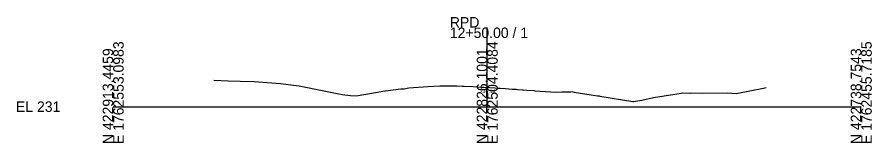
# Model space of a CAD drawing. Extents: x -26 to 203, y -10 to 3024.
# Drawn here: x -25.7 to 202.8, y 2990.3 to 3024 of the extents above; entities that cross this region are included whole.
import ezdxf

# ---------------------------------------------------------------- set-up
doc = ezdxf.new("R2010")
doc.units = 0
for name, color, linetype in [('Default', 7, 'Continuous'), ('Exist Cross Section Cell', 7, 'Continuous'), ('Exist XS Center Line Elevation Label', 7, 'Continuous'), ('Exist XS Ground Line', 7, 'Continuous')]:
    doc.layers.add(name, color=color, linetype=linetype)

msp = doc.modelspace()

# ---------------------------------------------------------------- linework, layer by layer
at = {"layer": 'Exist Cross Section Cell'}
for p, q in [((100, 3000), (100, 3021.18)), ((0, 3000), (100, 3000)), ((100, 3000), (200, 3000))]:
    msp.add_line(p, q, dxfattribs=at)
at = {"layer": 'Exist XS Ground Line'}
msp.add_lwpolyline([(26.9, 3007.06), (30.7, 3006.92), (33.97, 3006.82), (37.7, 3006.74), (44.76, 3006.21), (48.92, 3005.68), (49.74, 3005.54), (56.27, 3004.22), (61.19, 3003.3), (63.44, 3002.98), (64.97, 3002.87), (70.11, 3003.81), (72.64, 3004.25), (72.79, 3004.21), (76.9, 3004.78), (77.8, 3004.8), (79.03, 3005.08), (84.09, 3005.39), (87.33, 3005.54), (88.23, 3005.59), (88.43, 3005.59), (89.69, 3005.6), (90.59, 3005.6), (91.26, 3005.6), (91.31, 3005.6), (91.32, 3005.6), (91.84, 3005.58), (93.31, 3005.51), (93.46, 3005.5), (93.79, 3005.48), (96.28, 3005.36), (98.29, 3005.25), (98.82, 3005.22), (99.12, 3005.2), (100.67, 3005.1), (102.01, 3005.02), (102.53, 3004.99), (103.46, 3004.93), (104.89, 3004.83), (106.68, 3004.72), (107.72, 3004.65), (108.13, 3004.62), (109.39, 3004.54), (109.63, 3004.52), (110.59, 3004.44), (112.46, 3004.29), (112.53, 3004.29), (112.54, 3004.29), (112.69, 3004.28), (118.43, 3003.85), (119.95, 3004.02), (122.31, 3004.02), (122.62, 3004.06), (123.24, 3003.91), (129.52, 3002.93), (129.88, 3002.88), (130.13, 3002.84), (138.9, 3001.42), (139.19, 3001.38), (139.67, 3001.49), (141.29, 3001.76), (144.48, 3002.42), (150.13, 3003.33), (151.83, 3003.6), (152.2, 3003.68), (154.16, 3003.63), (154.25, 3003.62), (154.58, 3003.74), (157.57, 3003.58), (164.23, 3003.67), (166.53, 3003.55), (170.67, 3004.37), (173.88, 3004.96), (174.58, 3005.1)], dxfattribs=at)
msp.add_lwpolyline([(26.9, 3007.06), (30.7, 3006.92), (33.97, 3006.82), (37.7, 3006.74), (44.76, 3006.21), (48.92, 3005.68), (49.74, 3005.54), (56.27, 3004.22), (61.19, 3003.3), (63.44, 3002.98), (64.97, 3002.87), (70.11, 3003.81), (72.64, 3004.25), (72.79, 3004.21), (76.9, 3004.78), (77.8, 3004.8), (79.03, 3005.08), (84.09, 3005.39), (87.33, 3005.54), (88.23, 3005.59), (88.43, 3005.59), (89.69, 3005.6), (90.59, 3005.6), (91.26, 3005.6), (91.31, 3005.6), (91.32, 3005.6), (91.84, 3005.58), (93.31, 3005.51), (93.46, 3005.5), (93.79, 3005.48), (96.28, 3005.36), (98.29, 3005.25), (98.82, 3005.22), (99.12, 3005.2), (100.67, 3005.1), (102.01, 3005.02), (102.53, 3004.99), (103.46, 3004.93), (104.89, 3004.83), (106.68, 3004.72), (107.72, 3004.65), (108.13, 3004.62), (109.39, 3004.54), (109.63, 3004.52), (110.59, 3004.44), (112.46, 3004.29), (112.53, 3004.29), (112.54, 3004.29), (112.69, 3004.28), (118.43, 3003.85), (119.95, 3004.02), (122.31, 3004.02), (122.62, 3004.06), (123.24, 3003.91), (129.52, 3002.93), (129.88, 3002.88), (130.13, 3002.84), (138.9, 3001.42), (139.19, 3001.38), (139.67, 3001.49), (141.29, 3001.76), (144.48, 3002.42), (150.13, 3003.33), (151.83, 3003.6), (152.2, 3003.68), (154.16, 3003.63), (154.25, 3003.62), (154.58, 3003.74), (157.57, 3003.58), (164.23, 3003.67), (166.53, 3003.55), (170.67, 3004.37), (173.88, 3004.96), (174.58, 3005.1)], dxfattribs=at)

# ---------------------------------------------------------------- texts
at = {"layer": 'Default'}
for height in [0.0001, 0.000001, 0.0001]:
    msp.add_text('-', height=height, dxfattribs=at).set_placement((0, 3000))
at = {"layer": 'Exist Cross Section Cell'}
for s, p in [('RPD', (90, 3021.18)), ('12+50.00 / 1', (90, 3018.38)), ('EL 231', (-26, 2998.6))]:
    msp.add_text(s, height=2.8, dxfattribs=at).set_placement(p)
for s, p in [('E 1762553.0983', (2.8, 2990)), ('E 1762504.4084', (102.8, 2990)), ('E 1762455.7185', (202.8, 2990)), ('N 422913.4459', (0, 2990)), ('N 422826.1001', (100, 2990)), ('N 422738.7543', (200, 2990))]:
    msp.add_text(s, height=2.8, rotation=90, dxfattribs=at).set_placement(p)
at = {"layer": 'Exist XS Center Line Elevation Label'}
msp.add_text('236.14', height=1, dxfattribs=at).set_placement((97.98, 3003.64))

doc.saveas('drawing.dxf')
